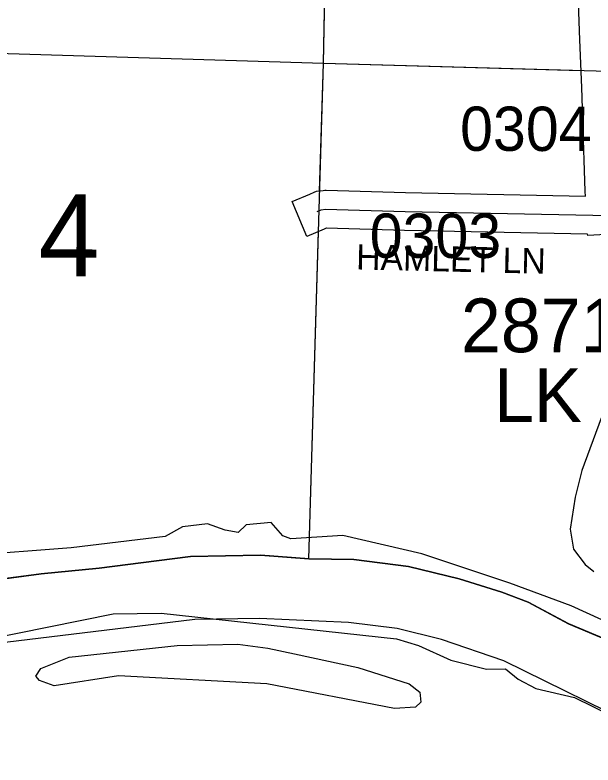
# Model space of a CAD drawing. Extents: x -132.8 to -73.3, y -60 to -26.
# Drawn here: x -125.183 to -124.268, y -45.375 to -44.188 of the extents above; entities that cross this region are included whole.
import ezdxf

# ---------------------------------------------------------------- set-up
doc = ezdxf.new("R2010")
doc.units = 0
for name, color, linetype in [('tdCoClipBndry', 7, 'Continuous'), ('tdCoCoBndry', 7, 'Continuous'), ('tdCoHydroRiver', 7, 'Continuous'), ('tdCoSecRdNmbr', 7, 'Continuous'), ('tdCoSecRdTxt', 7, 'Continuous'), ('tdCoSecRteBand', 7, 'Continuous'), ('tdCoSecRteCL', 7, 'Continuous'), ('tdCoSectLine', 7, 'Continuous'), ('tdCoSectLinePart', 7, 'Continuous'), ('tdCoSectNmbr', 7, 'Continuous'), ('tdCoStBndry', 7, 'Continuous'), ('tdCoStBndryPart', 7, 'Continuous'), ('tdCoStrucSecCoName', 7, 'Continuous'), ('tdCoStrucSecFHWANum', 7, 'Continuous'), ('tdCoSurfGravel', 7, 'Continuous'), ('tdCoTwpBndry', 7, 'Continuous'), ('tdCoTwpBndryShd', 7, 'Continuous')]:
    doc.layers.add(name, color=color, linetype=linetype)

msp = doc.modelspace()

# ---------------------------------------------------------------- linework, layer by layer
at = {"layer": 'tdCoClipBndry'}
msp.add_lwpolyline([(-124.0151, -45.4132), (-124.1267, -45.3442), (-124.1813, -45.322), (-124.4087, -45.21), (-124.5077, -45.1763), (-124.5779, -45.1592), (-124.6549, -45.1496), (-124.7958, -45.1431), (-124.898, -45.1449), (-125.2164, -45.1833), (-125.4103, -45.2357), (-125.7367, -45.238), (-125.885, -45.219), (-126.1143, -45.1325), (-126.5341, -44.8762), (-126.7711, -44.7076), (-127.1421, -44.4077)], dxfattribs=at)
at = {"layer": 'tdCoCoBndry'}
for p, q in [((-124.9582, -45.052), (-125.0492, -45.0634)), ((-124.9045, -45.045), (-124.9582, -45.052)), ((-124.7939, -45.0431), (-124.9045, -45.045)), ((-124.7171, -45.0488), (-124.7939, -45.0431)), ((-124.6461, -45.05), (-124.7171, -45.0488)), ((-124.5595, -45.0607), (-124.6461, -45.05)), ((-125.0492, -45.0634), (-125.1408, -45.0723)), ((-124.4793, -45.0802), (-124.5595, -45.0607)), ((-125.1408, -45.0723), (-125.2356, -45.0849)), ((-124.4117, -45.1017), (-124.4793, -45.0802)), ((-124.37, -45.1175), (-124.4117, -45.1017)), ((-124.3061, -45.1516), (-124.37, -45.1175)), ((-124.2467, -45.1762), (-124.3061, -45.1516))]:
    msp.add_line(p, q, dxfattribs=at)
for points in [[(-125.2359, -45.0849), (-125.1412, -45.0723), (-125.0496, -45.0634), (-124.9586, -45.052), (-124.9049, -45.045), (-124.7943, -45.0431), (-124.7175, -45.0488), (-124.6465, -45.05), (-124.5599, -45.0607), (-124.4797, -45.0802), (-124.412, -45.1017), (-124.3703, -45.1175), (-124.3065, -45.1516), (-124.2471, -45.1762), (-124.1789, -45.209), (-124.1372, -45.2324), (-124.0834, -45.2538), (-124.0216, -45.2888), (-123.9741, -45.3233), (-123.9526, -45.3347), (-123.8945, -45.3896)], [(-123.8941, -45.3896), (-123.9523, -45.3347), (-123.9737, -45.3233), (-124.0212, -45.2888), (-124.0831, -45.2538), (-124.1368, -45.2324), (-124.1785, -45.209), (-124.2467, -45.1762), (-124.3061, -45.1516), (-124.37, -45.1175), (-124.4117, -45.1017), (-124.4793, -45.0802), (-124.5595, -45.0607), (-124.6461, -45.05), (-124.7171, -45.0488), (-124.7939, -45.0431), (-124.9045, -45.045), (-124.9582, -45.052), (-125.0492, -45.0634), (-125.1408, -45.0723), (-125.2356, -45.0849)]]:
    msp.add_lwpolyline(points, dxfattribs=at)
at = {"layer": 'tdCoHydroRiver'}
for points in [[(-124.2545, -44.8263), (-124.2853, -44.909), (-124.296, -44.9513), (-124.3037, -45.0016), (-124.2983, -45.0333), (-124.28, -45.0575), (-124.2662, -45.0689)], [(-124.1262, -45.1975), (-124.1809, -45.1786), (-124.3024, -45.1231), (-124.3993, -45.0872), (-124.5384, -45.0406), (-124.6639, -45.0118), (-124.7461, -45.0173), (-124.7586, -45.0123), (-124.7769, -44.9912), (-124.8165, -44.9948), (-124.8295, -45.0071), (-124.8499, -45.0033), (-124.878, -44.9931), (-124.9176, -44.9983), (-124.9448, -45.0132), (-125.0937, -45.0311), (-125.2598, -45.0437)], [(-125.2812, -45.1867), (-125.0272, -45.1355), (-124.9515, -45.1345), (-124.5785, -45.1752), (-124.5441, -45.1856), (-124.4927, -45.2092), (-124.4363, -45.2234), (-124.4063, -45.2227), (-124.3862, -45.239), (-124.3582, -45.254), (-124.2971, -45.2684), (-124.2379, -45.2969), (-124.1528, -45.3577), (-124.072, -45.401)], [(-124.5817, -45.2855), (-124.7842, -45.2466), (-125.019, -45.2336), (-125.1205, -45.2496), (-125.1439, -45.2411), (-125.15, -45.2346), (-125.1418, -45.2222), (-125.0971, -45.2045), (-124.9261, -45.1858), (-124.8297, -45.1838), (-124.7826, -45.1899), (-124.7402, -45.1989), (-124.6398, -45.2207), (-124.5585, -45.2467), (-124.5415, -45.2598), (-124.5404, -45.2757), (-124.5485, -45.2833), (-124.5817, -45.2855)]]:
    msp.add_lwpolyline(points, dxfattribs=at)
at = {"layer": 'tdCoSecRteBand'}
msp.add_lwpolyline([(-124.2472, -44.5353), (-124.2759, -44.5369), (-124.2761, -44.5347), (-124.5658, -44.5291), (-124.5659, -44.5291), (-124.5661, -44.5291), (-124.6895, -44.5255), (-124.6899, -44.5256), (-124.693, -44.5268), (-124.7206, -44.5384), (-124.7438, -44.483), (-124.7161, -44.4715), (-124.7093, -44.4686), (-124.7056, -44.4671), (-124.7015, -44.4666), (-124.6948, -44.4657), (-124.6924, -44.4654), (-124.6901, -44.4655), (-124.5645, -44.4692), (-124.2795, -44.4746), (-124.2799, -44.4674), (-124.2799, -44.467), (-124.2799, -44.4667), (-124.2836, -44.3528), (-124.2855, -44.3031), (-124.2883, -44.2274), (-124.2883, -44.2273), (-124.2883, -44.2273), (-124.2925, -44.1102)], dxfattribs=at)
at = {"layer": 'tdCoSecRteCL'}
msp.add_lwpolyline([(-124.7045, -44.4991), (-124.6978, -44.4963), (-124.691, -44.4955), (-124.5652, -44.4991), (-124.268, -44.5048), (-124.2477, -44.5053)], dxfattribs=at)
at = {"layer": 'tdCoSectLine'}
for points in [[(-124.6944, -44.2641), (-124.6751, -43.2734)], [(-125.6932, -44.234), (-124.6944, -44.2641)], [(-124.7175, -45.0488), (-124.6944, -44.2641)], [(-124.6944, -44.2641), (-123.6992, -44.2925)], [(-125.7306, -45.1382), (-125.5423, -45.1362), (-125.4198, -45.1362), (-125.32, -45.1064), (-125.2359, -45.0849), (-125.1412, -45.0723), (-125.0496, -45.0634), (-124.9586, -45.052), (-124.9049, -45.045), (-124.7943, -45.0431), (-124.7175, -45.0488)], [(-124.7175, -45.0488), (-124.6465, -45.05), (-124.5599, -45.0607), (-124.4797, -45.0802), (-124.412, -45.1017), (-124.3703, -45.1175), (-124.3065, -45.1516), (-124.2471, -45.1762), (-124.1789, -45.209), (-124.1372, -45.2324), (-124.0834, -45.2538), (-124.0216, -45.2888)]]:
    msp.add_lwpolyline(points, dxfattribs=at)
at = {"layer": 'tdCoSectLinePart'}
for points in [[(-124.6944, -44.2641), (-124.6803, -43.5368)], [(-125.6932, -44.234), (-124.6944, -44.2641)], [(-124.7004, -44.4667), (-124.6944, -44.2641)], [(-124.6944, -44.2641), (-124.2868, -44.2758)], [(-124.7175, -45.0488), (-124.7023, -44.5306)], [(-125.7306, -45.1382), (-125.5423, -45.1362), (-125.4198, -45.1362), (-125.32, -45.1064), (-125.2359, -45.0849), (-125.1412, -45.0723), (-125.0496, -45.0634), (-124.9586, -45.052), (-124.9049, -45.045), (-124.7943, -45.0431), (-124.7175, -45.0488)], [(-124.7175, -45.0488), (-124.6465, -45.05), (-124.5599, -45.0607), (-124.4797, -45.0802), (-124.412, -45.1017), (-124.3703, -45.1175), (-124.3065, -45.1516), (-124.2471, -45.1762), (-124.1789, -45.209), (-124.1372, -45.2324), (-124.0834, -45.2538), (-124.0216, -45.2888)]]:
    msp.add_lwpolyline(points, dxfattribs=at)
at = {"layer": 'tdCoStBndry'}
msp.add_lwpolyline([(-125.2359, -45.0849), (-125.1412, -45.0723), (-125.0496, -45.0634), (-124.9586, -45.052), (-124.9049, -45.045), (-124.7943, -45.0431), (-124.7175, -45.0488), (-124.6465, -45.05), (-124.5599, -45.0607), (-124.4797, -45.0802), (-124.412, -45.1017), (-124.3703, -45.1175), (-124.3065, -45.1516), (-124.2471, -45.1762), (-124.1789, -45.209), (-124.1372, -45.2324), (-124.0834, -45.2538), (-124.0216, -45.2888), (-123.9741, -45.3233), (-123.9526, -45.3347), (-123.8945, -45.3896)], dxfattribs=at)
at = {"layer": 'tdCoStBndryPart'}
msp.add_lwpolyline([(-125.2359, -45.0849), (-125.1412, -45.0723), (-125.0496, -45.0634), (-124.9586, -45.052), (-124.9049, -45.045), (-124.7943, -45.0431), (-124.7175, -45.0488), (-124.6465, -45.05), (-124.5599, -45.0607), (-124.4797, -45.0802), (-124.412, -45.1017), (-124.3703, -45.1175), (-124.3065, -45.1516), (-124.2471, -45.1762), (-124.1789, -45.209), (-124.1372, -45.2324), (-124.0834, -45.2538), (-124.0216, -45.2888), (-123.9741, -45.3233), (-123.9526, -45.3347), (-123.8945, -45.3896)], dxfattribs=at)
at = {"layer": 'tdCoSurfGravel'}
msp.add_lwpolyline([(-124.7045, -44.4991), (-124.6978, -44.4963), (-124.691, -44.4955), (-124.5652, -44.4991), (-124.268, -44.5048), (-124.2477, -44.5053)], dxfattribs=at)
at = {"layer": 'tdCoTwpBndry'}
msp.add_lwpolyline([(-127.1145, -44.1981), (-126.6973, -44.2087), (-125.6932, -44.234), (-124.6944, -44.2641), (-124.2869, -44.2758)], dxfattribs=at)
at = {"layer": 'tdCoTwpBndryShd'}
for points in [[(-127.2202, -44.1954), (-126.6973, -44.2087), (-125.6932, -44.234), (-124.6944, -44.2641), (-123.6992, -44.2925), (-122.7152, -44.3247), (-121.7221, -44.3617), (-120.7507, -44.3901), (-119.7594, -44.4268), (-118.768, -44.449), (-117.7739, -44.4798), (-116.7726, -44.5066), (-115.7834, -44.5349), (-114.8143, -44.5585)], [(-123.8945, -45.3896), (-123.9526, -45.3347), (-123.9741, -45.3233), (-124.0216, -45.2888), (-124.0834, -45.2538), (-124.1372, -45.2324), (-124.1789, -45.209), (-124.2471, -45.1762), (-124.3065, -45.1516), (-124.3703, -45.1175), (-124.412, -45.1017), (-124.4797, -45.0802), (-124.5599, -45.0607), (-124.6465, -45.05), (-124.7175, -45.0488), (-124.7943, -45.0431), (-124.9049, -45.045), (-124.9586, -45.052), (-125.0496, -45.0634), (-125.1412, -45.0723), (-125.2359, -45.0849)]]:
    msp.add_lwpolyline(points, dxfattribs=at)

# ---------------------------------------------------------------- texts
at = {"layer": 'tdCoSecRdNmbr'}
for s, rotation, p in [('0304', 359.9071, (-124.4781, -44.403)), ('0303', 359.9068, (-124.6212, -44.5723))]:
    msp.add_text(s, height=0.07, rotation=rotation, dxfattribs=at).set_placement(p)
at = {"layer": 'tdCoSecRdTxt'}
msp.add_text('HAMLET LN', height=0.04, rotation=358.6684, dxfattribs=at).set_placement((-124.6429, -44.5907))
at = {"layer": 'tdCoSectNmbr'}
msp.add_text('4', height=0.13, rotation=359.9064, dxfattribs=at).set_placement((-125.1458, -44.6016))
at = {"layer": 'tdCoStrucSecCoName'}
msp.add_text('LK 1', height=0.085, dxfattribs=at).set_placement((-124.4243, -44.8321))
at = {"layer": 'tdCoStrucSecFHWANum'}
msp.add_text('287121', height=0.085, dxfattribs=at).set_placement((-124.4767, -44.7218))

doc.saveas('drawing.dxf')
